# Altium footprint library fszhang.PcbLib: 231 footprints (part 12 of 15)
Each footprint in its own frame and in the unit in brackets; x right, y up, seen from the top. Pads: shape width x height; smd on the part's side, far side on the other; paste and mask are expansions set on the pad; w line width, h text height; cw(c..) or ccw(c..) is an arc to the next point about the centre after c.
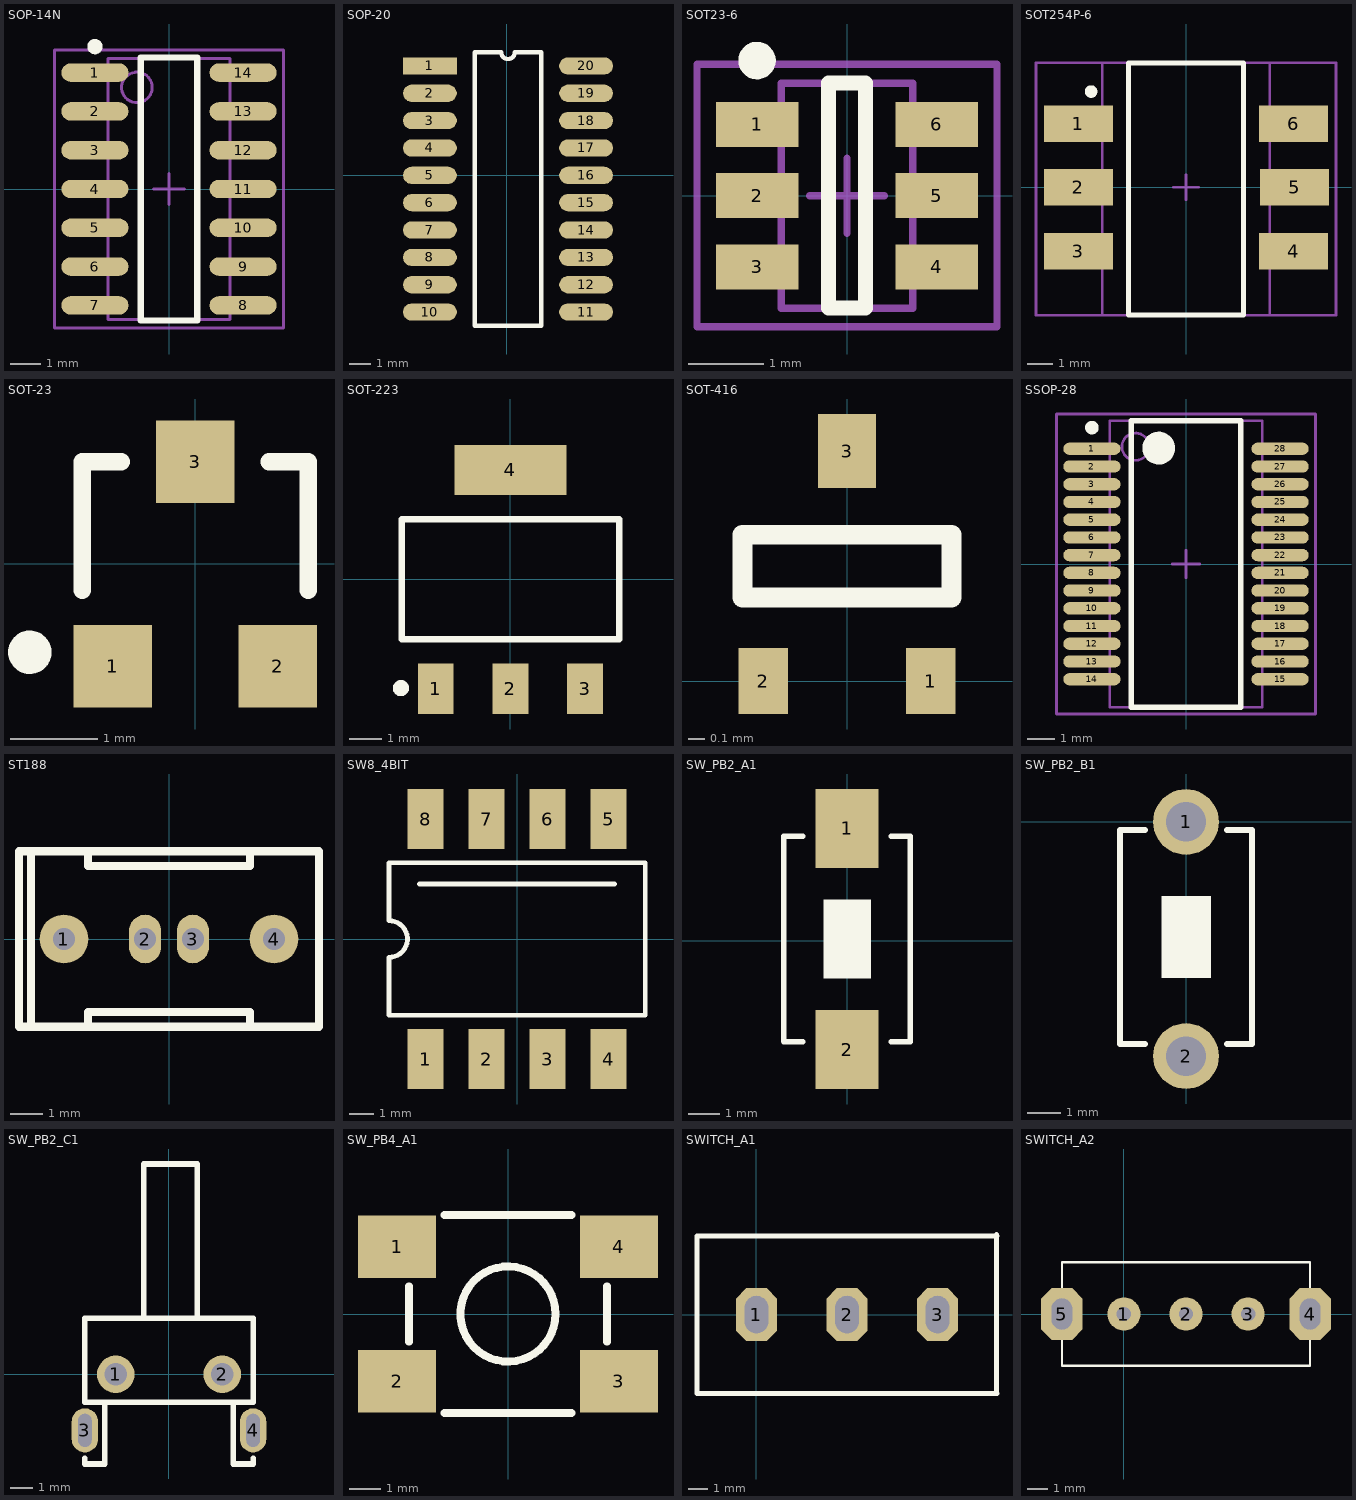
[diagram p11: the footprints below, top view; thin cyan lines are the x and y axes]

## SOP-14N [mm] "SOP, 14-Leads,"
height 1.75
pads (14):
  oval 2.2x0.6 smd: 1(-2.425,3.81) 2(-2.425,2.54) 3(-2.425,1.27) 4(-2.425,0) 5(-2.425,-1.27) 6(-2.425,-2.54) 7(-2.425,-3.81) 8(2.425,-3.81) 9(2.425,-2.54) 10(2.425,-1.27) 11(2.425,0) 12(2.425,1.27) 13(2.425,2.54) 14(2.425,3.81)
Top Overlay:
  circle w0.25: c-2.425,4.66 r0.125
  lines w0.2: -0.925,-4.3 -0.925,4.3 0.925,4.3 0.925,-4.3 -0.925,-4.3
Mechanical 13:
  circle w0.1: c-1.05,3.325 r0.5
  lines w0.1: -2,-4.275 -2,4.275 2,4.275 2,-4.275 -2,-4.275
Mechanical 15:
  lines w0.1: -0.5,0 0.5,0 ; 0,-0.5 0,0.5 ; -3.75,-4.55 -3.75,4.55 3.75,4.55 3.75,-4.55 -3.75,-4.55
3D body: height 1.75, standoff 0.2, extent -2,-4.275 2,4.275

## SOP-20 [mm] "74ls244"
height 2.032
pads (20):
  rect 2.5x0.8 smd: 1(-3.556,5.08)
  oval 2.5x0.8 smd: 2(-3.556,3.81) 3(-3.556,2.54) 4(-3.556,1.27) 5(-3.556,0) 6(-3.556,-1.27) 7(-3.556,-2.54) 8(-3.556,-3.81) 9(-3.556,-5.08) 10(-3.556,-6.35) 11(3.694,-6.35) 12(3.694,-5.08) 13(3.694,-3.81) 14(3.694,-2.54) 15(3.694,-1.27) 16(3.694,0) 17(3.694,1.27) 18(3.694,2.54) 19(3.694,3.81) 20(3.694,5.08)
Top Overlay:
  lines w0.2: -1.471,-6.985 1.609,-6.985 1.609,5.715 0.386,5.715 cw(c0.069,5.715) -0.249,5.715 -1.471,5.715 -1.471,-6.985

## SOT23-6 [mm] "Max4173"
height 1.45
pads (6):
  rect 1.1x0.6 smd: 1(-1.2,0.95) 2(-1.2,0) 3(-1.2,-0.95) 4(1.2,-0.95) 5(1.2,0) 6(1.2,0.95)
Top Overlay:
  circle w0.25: c-1.2,1.8 r0.125
  lines w0.2: -0.25,-1.5 0.25,-1.5 0.25,1.5 -0.25,1.5 -0.25,-1.5
Mechanical 13:
  lines w0.1: -0.875,-1.5 -0.875,1.5 0.875,1.5 0.875,-1.5 -0.875,-1.5
Mechanical 15:
  lines w0.1: -0.5,0 0.5,0 ; 0,-0.5 0,0.5 ; -2,-1.75 -2,1.75 2,1.75 2,-1.75 -2,-1.75
3D body: height 1.45, standoff 0, extent -0.875,-1.5 0.875,1.5

## SOT254P-6 [mm] "继电器"
height 3.8
pads (6):
  rect 2.75x1.45 smd: 1(-4.283,2.54) 2(-4.283,0) 3(-4.283,-2.54) 4(4.283,-2.54) 5(4.318,0) 6(4.283,2.54)
Top Overlay:
  circle w0.25: c-3.775,3.815 r0.125
  lines w0.2: -2.286,-5.08 2.286,-5.08 2.286,4.953 -2.286,4.953 -2.286,-5.08
Mechanical 13:
  lines w0.1: -3.325,-5.08 -3.325,4.953 3.325,4.953 3.325,-5.08 -3.325,-5.08
Mechanical 15:
  lines w0.1: -0.5,0 0.5,0 ; 0,-0.5 0,0.5 ; -5.969,-5.08 -5.969,4.953 5.969,4.953 5.969,-5.08 -5.969,-5.08
3D body: height 3.8, standoff 0.05, extent -3.325,-5.08 3.325,4.953

## SOT-23 [mm]
height 1.1
pads (3):
  rect 0.9x0.95 smd: 1(-0.95,-1.175) 2(0.95,-1.175) 3(0,1.175)
Top Overlay:
  circle w0.25: c-1.903,-1.016 r0.125
  lines w0.2: -1.3,-0.3 -1.3,1.175 -0.85,1.175 ; 0.85,1.175 1.3,1.175 1.3,-0.3

## SOT-223 [mm]
height 1.8
pads (4):
  rect 1.1x1.55 smd: 1(-2.3,-3.375) 2(0,-3.375) 3(2.3,-3.375)
  rect 3.45x1.55 smd: 4(0,3.375)
Top Overlay:
  circle w0.25: c-3.376,-3.353 r0.125
  lines w0.2: -3.35,-1.85 -3.35,1.85 3.35,1.85 3.35,-1.85 -3.35,-1.85
3D body: height 0.8, standoff 0, extent -3.302,-2.032 3.302,2.159
3D body: height 0.3, standoff 0, extent -1.651,2.159 1.651,3.429
3D body: height 0.3, standoff 0, extent -2.794,-3.937 -1.905,-2.032
3D body: height 0.3, standoff 0, extent -0.508,-3.937 0.381,-2.032
3D body: height 0.3, standoff 0, extent 1.905,-3.937 2.794,-2.032

## SOT-416 [mm]
height 0.7
pads (3):
  rect 0.3x0.4 smd: 1(0.508,0) 2(-0.508,0)
  rect 0.35x0.45 smd: 3(0,1.397)
Top Overlay:
  lines w0.12: -0.635,0.508 -0.635,0.889 0.635,0.889 0.635,0.508 -0.635,0.508

## SSOP-28 [mm] "FT232"
height 2
pads (28):
  oval 2.1x0.45 smd: 1(-3.45,4.225) 2(-3.45,3.575) 3(-3.45,2.925) 4(-3.45,2.275) 5(-3.45,1.625) 6(-3.45,0.975) 7(-3.45,0.325) 8(-3.45,-0.325) 9(-3.45,-0.975) 10(-3.45,-1.625) 11(-3.45,-2.275) 12(-3.45,-2.925) 13(-3.45,-3.575) 14(-3.45,-4.225) 15(3.45,-4.225) 16(3.45,-3.575) 17(3.45,-2.925) 18(3.45,-2.275) 19(3.45,-1.625) 20(3.45,-0.975) 21(3.45,-0.325) 22(3.45,0.325) 23(3.45,0.975) 24(3.45,1.625) 25(3.45,2.275) 26(3.45,2.925) 27(3.45,3.575) 28(3.45,4.225)
Top Overlay:
  circle w0.25: c-3.45,5 r0.125
  circle w0.6: c-1,4.25 r0.3
  lines w0.2: -2,-5.25 -2,5.25 2,5.25 2,-5.25 -2,-5.25
Mechanical 13:
  circle w0.1: c-1.85,4.3 r0.5
  lines w0.1: -2.8,-5.25 -2.8,5.25 2.8,5.25 2.8,-5.25 -2.8,-5.25
Mechanical 15:
  lines w0.1: -0.5,0 0.5,0 ; 0,-0.5 0,0.5 ; -4.75,-5.5 -4.75,5.5 4.75,5.5 4.75,-5.5 -4.75,-5.5
3D body: height 2, standoff 0.09, extent -2.8,-5.25 2.8,5.25

## ST188 [mm] "反射式光电传感器"
height 8.2
pads (4):
  round 1.524 hole 0.7: 1(-3.29,0) 4(3.29,0)
  oval 1x1.524 hole 0.7: 2(-0.75,0) 3(0.75,0)
Top Overlay:
  lines w0.254: -4.318,-2.75 -4.318,2.75 ; -2.54,-2.75 -2.54,-2.286 2.54,-2.286 2.54,-2.75 ; -2.54,2.75 -2.54,2.286 2.54,2.286 2.54,2.75 ; -4.7,-2.75 -4.7,2.75 4.7,2.75 4.7,-2.75 -4.7,-2.75

## SW8_4BIT [mm] "贴片拨码开关"
height 1.75
pads (8):
  rect 1.5x2.5 smd: 1(-3.81,-5) 2(-1.27,-5) 3(1.27,-5) 4(3.81,-5) 5(3.81,5) 6(1.27,5) 7(-1.27,5) 8(-3.81,5)
Top Overlay:
  lines w0.2: -4.064,2.286 4.064,2.286 ; -5.334,-3.175 5.334,-3.175 5.334,3.175 -5.334,3.175 -5.334,0.762 cw(c-5.334,0) -5.334,-0.762 -5.334,-3.175
3D body: height 2.15, standoff 2.05, extent 3.048,0.889 4.572,2.413
3D body: height 2.15, standoff 2.05, extent 0.508,0.889 2.032,2.413
3D body: height 2.15, standoff 2.05, extent -2.032,-2.032 -0.508,-0.508
3D body: height 2.15, standoff 2.05, extent -4.572,0.889 -3.048,2.413
3D body: height 2.05, standoff 2, extent 3.048,-2.032 4.572,2.413
3D body: height 2.05, standoff 2, extent 0.508,-2.032 2.032,2.413
3D body: height 2.05, standoff 2, extent -2.032,-2.032 -0.508,2.413
3D body: height 2.05, standoff 2, extent -4.572,-2.032 -3.048,2.413
3D body: height 2, standoff 0, extent -5.207,-3.429 5.08,3.429

## SW_PB2_A1 [mm]
pads (2):
  rect 2x2.5 smd: 1(0,3.556) 2(0,-3.444)
Top Overlay:
  region: -0.747,1.309 -0.747,-1.191 0.753,-1.191 0.753,1.309
  lines w0.178: -1.397,-3.193 -2,-3.19 -2,3.306 -1.397,3.306 ; 1.397,-3.194 2,-3.194 2,3.306 1.397,3.306
3D body: height 1.2, standoff 0.8, extent -0.762,-1.143 0.762,1.27
3D body: height 0.8, standoff 0, extent -2.032,-3.175 2.032,3.302

## SW_PB2_B1 [mm]
pads (2):
  round 2 hole 1.2: 1(0,0) 2(0,-7.112)
Top Overlay:
  region: -0.747,-2.247 -0.747,-4.747 0.753,-4.747 0.753,-2.247
  lines w0.178: -1.25,-6.75 -2,-6.746 -2,-0.25 -1.25,-0.25 ; 1.25,-6.75 2,-6.75 2,-0.25 1.25,-0.25

## SW_PB2_C1 [mm] "侧卧微动开关"
height 8
pads (4):
  round 1.7 hole 1: 1(-2.413,0) 2(2.413,0)
  oval 1.2x2 hole 0.6 slot 1.5 at 90 deg: 3(-3.81,-2.54) 4(3.81,-2.54)
Top Overlay:
  lines w0.25: -3.81,-3.81 -3.81,-4.064 -2.921,-4.064 -2.921,-1.27 ; -1.143,2.54 -1.143,9.525 1.27,9.525 1.27,2.54 ; 2.921,-1.27 2.921,-4.064 3.81,-4.064 3.81,-3.81 ; -3.81,-1.27 -3.81,2.54 3.81,2.54 3.81,-1.27 -3.81,-1.27

## SW_PB4_A1 [mm]
pads (4):
  rect 2.5x2 smd: 1(-3.556,2.159) 2(-3.556,-2.159) 3(3.556,-2.159) 4(3.556,2.159)
Top Overlay:
  circle w0.254: c0,0 r1.524
  lines w0.25: -3.175,-0.889 -3.175,0.889 ; -2.032,-3.175 2.032,-3.175 ; -2.032,3.175 2.032,3.175 ; 3.175,-0.889 3.175,0.889
3D body: height 6, standoff 0, extent -1.524,-1.524 1.524,1.524
3D body: height 1.5, standoff 0, extent -3.175,-3.175 3.175,3.175

## SWITCH_A1 [mm] "扭子开关"
height 10
pads (3):
  oct 2.1x2.7 hole 1.2 slot 1.9 at 90 deg: 1(0,0) 2(4.6,0) 3(9.2,0)
Top Overlay:
  lines w0.254: 12.192,-3.972 12.192,4.064 ; 12.22,-4 -3.02,-4 -3.02,4 12.22,4

## SWITCH_A2 [mm] "平拨开关"
height 9
pads (5):
  round 1.6 hole 0.7: 1(0,0) 2(3,0) 3(6,0)
  oct 2x2.5 hole 1 slot 1.5 at 90 deg: 4(9,0) 5(-3,0)
Top Overlay:
  lines w0.1: -3,-2.5 -3,2.5 9,2.5 9,-2.5 -3,-2.5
